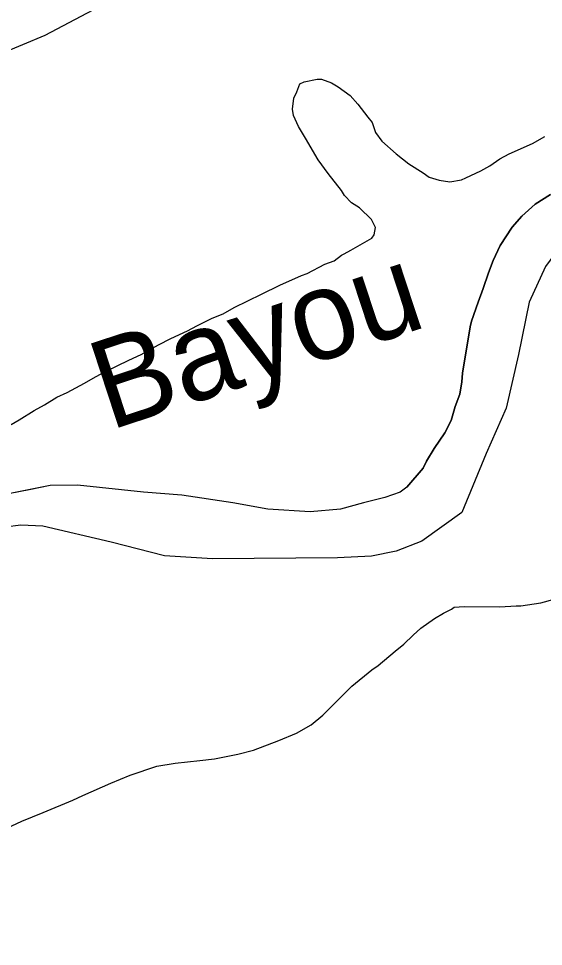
# Model space of a CAD drawing. Extents: x 3192986 to 3230865, y 867483 to 892886.
# Drawn here: x 3215774 to 3216460, y 883342 to 884557 of the extents above; entities that cross this region are included whole.
import ezdxf

# ---------------------------------------------------------------- set-up
doc = ezdxf.new("R2010")
doc.units = 0
for name, color, linetype in [('V-RIVR-IDEN', 7, 'Continuous'), ('V-SITE-VEGE', 7, 'Continuous'), ('V-TOPO-SHOR', 7, 'Continuous')]:
    doc.layers.add(name, color=color, linetype=linetype)

msp = doc.modelspace()

# ---------------------------------------------------------------- linework, layer by layer
at = {"layer": 'V-SITE-VEGE'}
for p, q in [((3216147.4, 884473.7), (3216164.4, 884477.2)), ((3216164.4, 884477.2), (3216170, 884477.1)), ((3216170, 884477.1), (3216183.1, 884472.2)), ((3216137.8, 884460.6), (3216141.7, 884471)), ((3216141.7, 884471), (3216147.4, 884473.7)), ((3216183.1, 884472.2), (3216191.6, 884467.4)), ((3216191.6, 884467.4), (3216207.4, 884455.9)), ((3216131.8, 884438.1), (3216133.9, 884452.2)), ((3216133.9, 884452.2), (3216137.8, 884460.6)), ((3216207.4, 884455.9), (3216217.6, 884444.4)), ((3216133.5, 884429.6), (3216131.8, 884438.1)), ((3216217.6, 884444.4), (3216230.6, 884427.3)), ((3216139.9, 884415.4), (3216133.5, 884429.6)), ((3216230.6, 884427.3), (3216236.1, 884420.6)), ((3216149.1, 884400.2), (3216139.9, 884415.4)), ((3216236.1, 884420.6), (3216240.6, 884407.3)), ((3216240.6, 884407.3), (3216249, 884395.9)), ((3216445.8, 884393.1), (3216462, 884402.3)), ((3216165.7, 884371.7), (3216149.1, 884400.2)), ((3216249, 884395.9), (3216267.6, 884379.6)), ((3216415.5, 884379.4), (3216445.8, 884393.1)), ((3216267.6, 884379.6), (3216284.3, 884366.2)), ((3216403.1, 884373), (3216415.5, 884379.4)), ((3216178.6, 884353.6), (3216165.7, 884371.7)), ((3216284.3, 884366.2), (3216303, 884354.6)), ((3216389.8, 884363.7), (3216403.1, 884373)), ((3216196.2, 884331.7), (3216178.6, 884353.6)), ((3216303, 884354.6), (3216310.5, 884348.9)), ((3216358.5, 884348.2), (3216378.4, 884357.3)), ((3216378.4, 884357.3), (3216389.8, 884363.7)), ((3216310.5, 884348.9), (3216323.6, 884344.9)), ((3216323.6, 884344.9), (3216337.7, 884342.8)), ((3216337.7, 884342.8), (3216352.8, 884345.4)), ((3216352.8, 884345.4), (3216358.5, 884348.2)), ((3216199.9, 884325), (3216196.2, 884331.7)), ((3216209.2, 884315.5), (3216199.9, 884325)), ((3216469.2, 884326.4), (3216449.4, 884313.5)), ((3216219.4, 884308.7), (3216209.2, 884315.5)), ((3216235.2, 884293.4), (3216219.4, 884308.7)), ((3216449.4, 884313.5), (3216432, 884297.8)), ((3216240.7, 884283), (3216235.2, 884293.4)), ((3216432, 884297.8), (3216419.4, 884283.6)), ((3216238.7, 884273.6), (3216240.7, 884283)), ((3216419.4, 884283.6), (3216403.4, 884259.4)), ((3216208.3, 884253.3), (3216235.8, 884268.9)), ((3216235.8, 884268.9), (3216238.7, 884273.6)), ((3216403.4, 884259.4), (3216394.4, 884239.9)), ((3216186.4, 884239.5), (3216195.9, 884246.9)), ((3216195.9, 884246.9), (3216199.7, 884248.7)), ((3216199.7, 884248.7), (3216208.3, 884253.3)), ((3216151.3, 884223), (3216174.1, 884234.9)), ((3216174.1, 884234.9), (3216186.4, 884239.5)), ((3216394.4, 884239.9), (3216388.1, 884223.6)), ((3216462.8, 884231.8), (3216441.4, 884185.2)), ((3216115.3, 884207.5), (3216143.7, 884220.3)), ((3216143.7, 884220.3), (3216151.3, 884223)), ((3216388.1, 884223.6), (3216381.4, 884203.3)), ((3216091.5, 884195.6), (3216115.3, 884207.5)), ((3216055.5, 884178.2), (3216091.5, 884195.6)), ((3216381.4, 884203.3), (3216374.8, 884185.4)), ((3216374.8, 884185.4), (3216366, 884160.3)), ((3216441.4, 884185.2), (3216427.7, 884116.7)), ((3216041.2, 884169.9), (3216055.5, 884178.2)), ((3216007.1, 884154.4), (3216027, 884164.5)), ((3216027, 884164.5), (3216041.2, 884169.9)), ((3216366, 884160.3), (3216364.3, 884153.2)), ((3215972.9, 884137.9), (3215994.8, 884148)), ((3215994.8, 884148), (3216007.1, 884154.4)), ((3216364.3, 884153.2), (3216354.2, 884092.5)), ((3215956.8, 884129.7), (3215972.9, 884137.9)), ((3215934, 884116.8), (3215956.8, 884129.7)), ((3215917.9, 884109.5), (3215934, 884116.8)), ((3216427.7, 884116.7), (3216411.4, 884046.4)), ((3215888.5, 884094.9), (3215917.9, 884109.5)), ((3215860, 884079.3), (3215874.2, 884087.5)), ((3215874.2, 884087.5), (3215888.5, 884094.9)), ((3216354.2, 884092.5), (3216353.3, 884080.9)), ((3215837.2, 884067.3), (3215860, 884079.3)), ((3216353.3, 884080.9), (3216350.6, 884065)), ((3215823.9, 884060.9), (3215837.2, 884067.3)), ((3216350.6, 884065), (3216344.8, 884048.7)), ((3215794.4, 884043.4), (3215807.7, 884050.8)), ((3215807.7, 884050.8), (3215823.9, 884060.9)), ((3215774.5, 884031.5), (3215794.4, 884043.4)), ((3216344.8, 884048.7), (3216339.4, 884030.3)), ((3216411.4, 884046.4), (3216385.2, 883987.2)), ((3215764, 884025), (3215774.5, 884031.5)), ((3216339.4, 884030.3), (3216331.1, 884014.1)), ((3216331.1, 884014.1), (3216317.2, 883993.9)), ((3216317.2, 883993.9), (3216307.4, 883977.2)), ((3216307.4, 883977.2), (3216302.9, 883968.1)), ((3216385.2, 883987.2), (3216353.4, 883909.9)), ((3216302.9, 883968.1), (3216281.5, 883943.1)), ((3215815, 883945.3), (3215760.6, 883934.3)), ((3215850.9, 883945.7), (3215815, 883945.3)), ((3215937.3, 883936.7), (3215850.9, 883945.7)), ((3216281.5, 883943.1), (3216272.8, 883936.5)), ((3215987.2, 883932.5), (3215937.3, 883936.7)), ((3216053.9, 883922.5), (3215987.2, 883932.5)), ((3216252.8, 883929.6), (3216224.7, 883922.8)), ((3216272.8, 883936.5), (3216252.8, 883929.6)), ((3216099.9, 883914.6), (3216053.9, 883922.5)), ((3216224.7, 883922.8), (3216194.7, 883914.2)), ((3216154.9, 883911.1), (3216099.9, 883914.6)), ((3216194.7, 883914.2), (3216154.9, 883911.1)), ((3216353.4, 883909.9), (3216301.3, 883872.7)), ((3215776.9, 883893.6), (3215756.4, 883890.7)), ((3215805.6, 883892.3), (3215776.9, 883893.6)), ((3215895, 883871.4), (3215805.6, 883892.3)), ((3215964.8, 883853.1), (3215895, 883871.4)), ((3216301.3, 883872.7), (3216267.7, 883859.6)), ((3216267.7, 883859.6), (3216235.1, 883852.9)), ((3216027.2, 883849.5), (3215964.8, 883853.1)), ((3216190.8, 883850.8), (3216027.2, 883849.5)), ((3216235.1, 883852.9), (3216190.8, 883850.8)), ((3216456.5, 883792), (3216474, 883796.4)), ((3216329.5, 883778.2), (3216339.7, 883783.6)), ((3216339.7, 883783.6), (3216343.4, 883786.3)), ((3216343.4, 883786.3), (3216356.3, 883787)), ((3216356.3, 883787), (3216403.1, 883786.4)), ((3216403.1, 883786.4), (3216424.3, 883787.9)), ((3216424.3, 883787.9), (3216430.7, 883787.8)), ((3216430.7, 883787.8), (3216456.5, 883792)), ((3216299.9, 883758.5), (3216317.5, 883771.1)), ((3216317.5, 883771.1), (3216329.5, 883778.2)), ((3216289.6, 883749.4), (3216299.9, 883758.5)), ((3216277.5, 883737.7), (3216289.6, 883749.4)), ((3216266.4, 883728.6), (3216277.5, 883737.7)), ((3216244.1, 883709.7), (3216266.4, 883728.6)), ((3216235.7, 883704.3), (3216244.1, 883709.7)), ((3216209.7, 883682.6), (3216235.7, 883704.3)), ((3216193.9, 883667.2), (3216209.7, 883682.6)), ((3216171.5, 883644.6), (3216193.9, 883667.2)), ((3216156.6, 883631.9), (3216171.5, 883644.6)), ((3216137.2, 883621.2), (3216156.6, 883631.9)), ((3216114.1, 883611.4), (3216137.2, 883621.2)), ((3216080.8, 883599), (3216114.1, 883611.4)), ((3216010.8, 883585.3), (3216030.1, 883587.8)), ((3216030.1, 883587.8), (3216060.5, 883593.8)), ((3216060.5, 883593.8), (3216080.8, 883599)), ((3215919.6, 883566.4), (3215954.7, 883577.9)), ((3215954.7, 883577.9), (3215978.6, 883582.1)), ((3215978.6, 883582.1), (3216010.8, 883585.3)), ((3215894.6, 883555.8), (3215919.6, 883566.4)), ((3215857.7, 883539.8), (3215894.6, 883555.8)), ((3215844.7, 883533.5), (3215857.7, 883539.8)), ((3215805.9, 883517.5), (3215844.7, 883533.5)), ((3215778.2, 883506), (3215805.9, 883517.5)), ((3215739.4, 883488.2), (3215778.2, 883506))]:
    msp.add_line(p, q, dxfattribs=at)
at = {"layer": 'V-TOPO-SHOR'}
for points in [[(3215926.4, 884597.4), (3215808, 884534.3), (3215720.2, 884497.7), (3215668.3, 884483.9), (3215591.4, 884466.9), (3215441.4, 884450.5), (3215369.9, 884444), (3215296.8, 884446.5), (3215255.7, 884439.8), (3215235.9, 884427.5), (3215205.6, 884427.8), (3215175.2, 884419.2), (3215137.5, 884405.3), (3215117.9, 884403.7), (3215109, 884402), (3215057, 884379.3), (3214960, 884321.3), (3214909.6, 884275.4), (3214864.7, 884242)], [(3216281.5, 883943.1), (3216302.9, 883968.1), (3216307.4, 883977.2), (3216317.2, 883993.9), (3216331.1, 884014.1), (3216339.4, 884030.3), (3216344.8, 884048.7), (3216350.6, 884065), (3216353.3, 884080.9), (3216354.2, 884092.5), (3216364.3, 884153.2), (3216366, 884160.3), (3216374.8, 884185.4), (3216381.4, 884203.3), (3216388.1, 884223.6), (3216394.4, 884239.9), (3216403.4, 884259.4), (3216419.4, 884283.5), (3216432, 884297.8), (3216449.4, 884313.5), (3216469.2, 884326.4)], [(3217062.3, 884061.5), (3216835.3, 884183.1), (3216690.9, 884254.8), (3216628.8, 884276.4), (3216601.8, 884285.9), (3216584.7, 884288.8), (3216533.2, 884286.9), (3216505, 884278.2), (3216482.2, 884258.7), (3216462.8, 884231.8), (3216441.4, 884185.2), (3216427.7, 884116.7), (3216411.4, 884046.4), (3216385.2, 883987.2), (3216353.4, 883909.9), (3216301.3, 883872.7), (3216267.7, 883859.6), (3216235.1, 883852.9), (3216190.8, 883850.8), (3216027.2, 883849.5), (3215964.8, 883853.1)], [(3215937.3, 883936.7), (3215850.9, 883945.7), (3215815, 883945.3), (3215787.6, 883939.8), (3215760.6, 883934.3)], [(3216281.5, 883943.1), (3216272.8, 883936.5), (3216252.8, 883929.6), (3216224.7, 883922.8), (3216194.7, 883914.2), (3216154.9, 883911.1), (3216099.9, 883914.6), (3216053.9, 883922.5), (3215987.2, 883932.5), (3215937.3, 883936.7)], [(3215964.8, 883853.1), (3215895, 883871.4), (3215805.6, 883892.3), (3215776.9, 883893.6), (3215756.4, 883890.7)]]:
    msp.add_lwpolyline(points, dxfattribs=at)
msp.add_spline([(3220607.9, 883199.2), (3220556.6, 882928.6), (3220515.7, 882851.2), (3220465.6, 882706.2), (3220430.9, 882570.1), (3220379.2, 882505.8), (3220271.9, 882419.1), (3220211.6, 882387.8), (3220155.9, 882347.3), (3220040.6, 882280.2), (3219987.2, 882238.8), (3219928.3, 882210.2), (3219791.8, 882190.3), (3219596.9, 882186.8), (3219449.9, 882236.7), (3219382.4, 882236.9), (3219259.1, 882200.6), (3219196.3, 882193.2), (3219122.1, 882181.5), (3219060, 882164.8), (3218928.8, 882172.5), (3218797.4, 882170), (3218655, 882208.7), (3218507.4, 882275), (3218436.3, 882298.3), (3218372.7, 882345.8), (3218248.1, 882507.7), (3218204, 882564.3), (3218139.8, 882611.1), (3218066.6, 882648.9), (3218002.7, 882654), (3217945.7, 882626.2), (3217854.1, 882485.8), (3217751.1, 882382.9), (3217706.7, 882304.3), (3217684.4, 882231.9), (3217658.8, 882027.8), (3217607.4, 881968.1), (3217545.8, 881963.9), (3217403, 881998.1), (3217345.4, 881975), (3217238.8, 881893.4), (3217179.3, 881868.5), (3217112.2, 881868.3), (3216902.2, 881905.6), (3216773.3, 881906.4), (3216626.2, 881977), (3216554.8, 882004.2), (3216487.5, 882014.3), (3216412, 882043.2), (3216346.8, 882045.6), (3216319, 882038.1), (3216297.4, 882015.2), (3216166.6, 882007.7), (3216039.6, 881975.8), (3215985, 881942.7), (3215950.8, 881866.5), (3215944.2, 881801.5), (3215938, 881733.2), (3215887.7, 881682.8), (3215768.7, 881641.4), (3215640.8, 881623.2), (3215558.6, 881662.6), (3215466.9, 881717.1), (3215359.5, 881762.4), (3215352.6, 881880.7), (3215338.7, 881992), (3215296.9, 882158.9), (3215310.8, 882249.4), (3215296.9, 882339.8), (3215331.7, 882409.4), (3215394.3, 882534.6), (3215429.1, 882687.6), (3215456.9, 882785), (3215436.1, 882840.7), (3215429.1, 882896.3), (3215430, 882941.3), (3215392.3, 882993.6), (3215270.5, 883089.5), (3215204.8, 883100.5), (3215141.6, 883148.3), (3215155.2, 883215), (3215200, 883290.4), (3215187.9, 883417.1), (3215237.3, 883490.8), (3215287.5, 883538.3), (3215287.7, 883538.5)], degree=3, dxfattribs=at)

# ---------------------------------------------------------------- texts
at = {"layer": 'V-RIVR-IDEN'}
msp.add_text('Bayou', height=116, rotation=18.166, dxfattribs=at).set_placement((3215892.6, 884017.1))

doc.saveas('drawing.dxf')
